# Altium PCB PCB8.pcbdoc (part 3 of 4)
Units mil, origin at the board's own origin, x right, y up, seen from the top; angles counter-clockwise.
Board outline 6799.06 x 5716.8 mil, 2 copper layers (Top Layer, Bottom Layer); 312 components, 374 nets, 1333 pads, 994 vias.
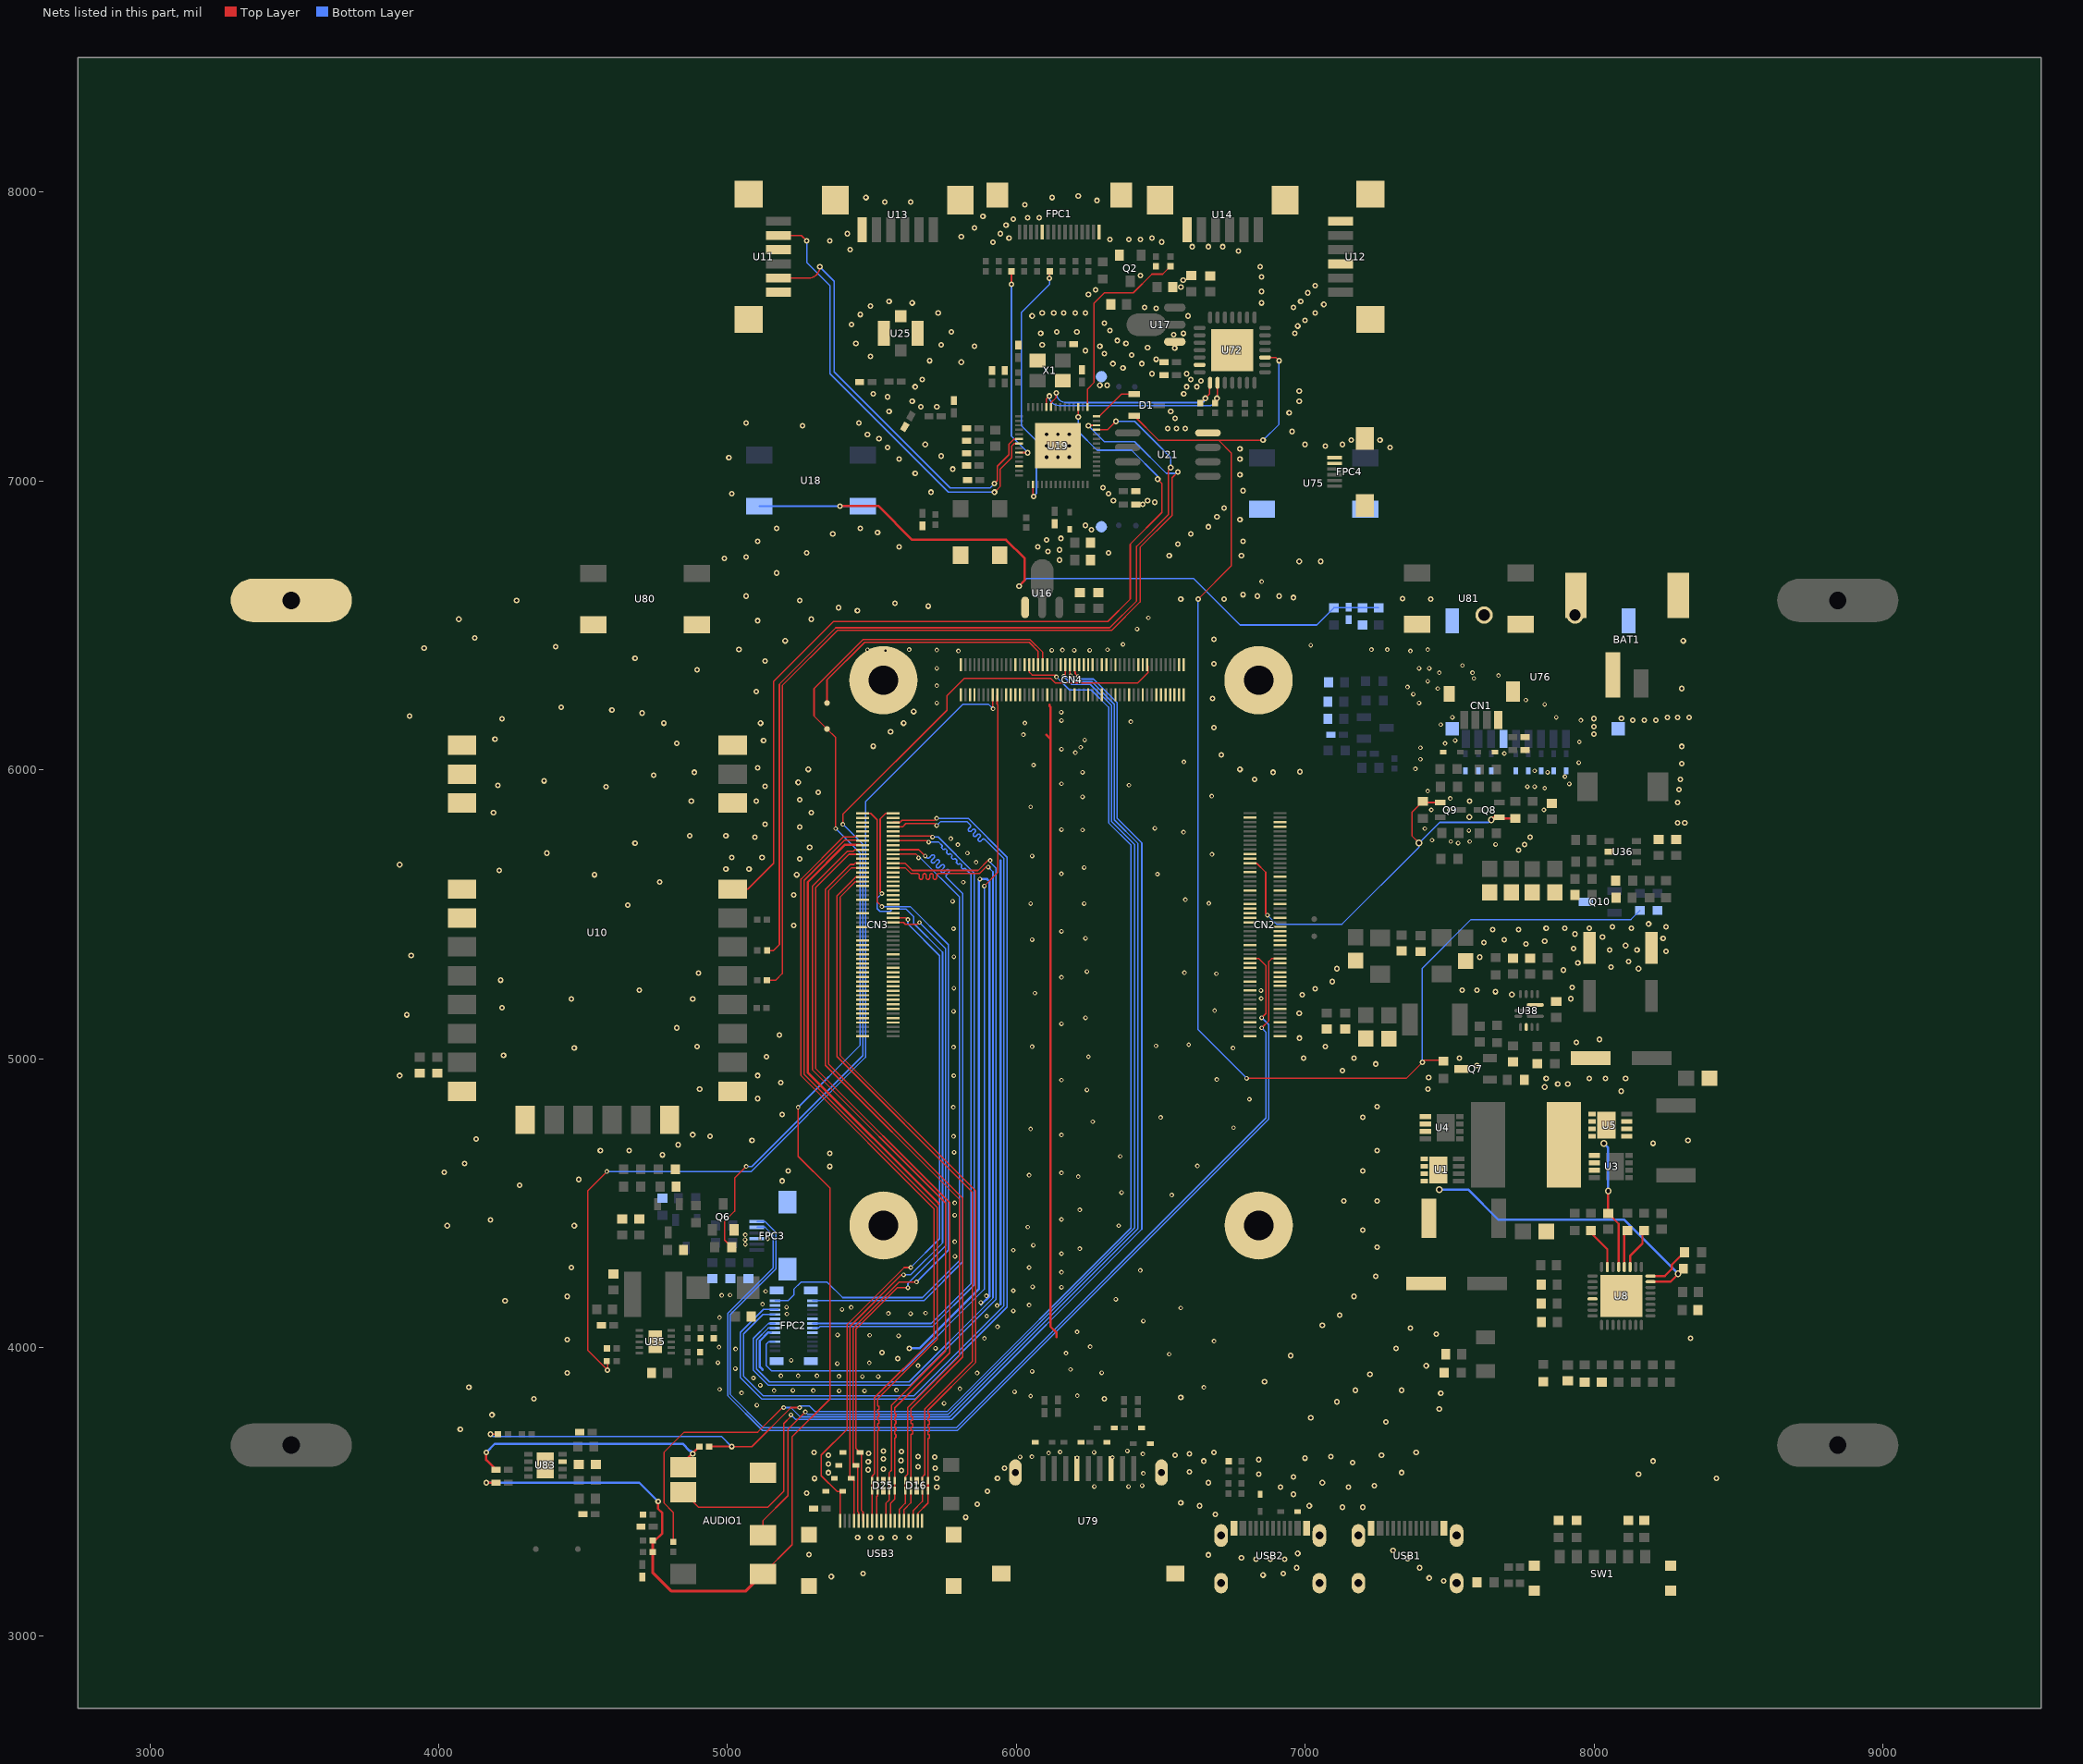
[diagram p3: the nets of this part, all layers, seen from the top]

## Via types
v1: diameter 19.7, hole 9.84, Top Layer to Bottom Layer, 526 vias
v2: diameter 15.75, hole 7.87, Top Layer to Bottom Layer, 322 vias
v3: diameter 19.68, hole 9.84, Top Layer to Bottom Layer, 98 vias
v4: diameter 23.62, hole 13.78, Top Layer to Bottom Layer, 39 vias
v5: diameter 24, hole 12, Top Layer to Bottom Layer, 9 vias

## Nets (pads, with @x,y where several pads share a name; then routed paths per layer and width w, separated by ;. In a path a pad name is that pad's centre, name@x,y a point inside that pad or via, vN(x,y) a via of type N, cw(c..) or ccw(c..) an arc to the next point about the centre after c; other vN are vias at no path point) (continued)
GND: BAT1.2 BAT1.3 BAT1.4 boot1.2 boot.2 C1.1 C2.1 C3.1 C7.1 C9.1 C10.2 C11.1 C12.2 C17.1 C18.1 C19.1 C20.1 C21.1 C22.1 C23.1 C24.1 C25.1 C26.1 C27.1 C30.2 C37.1 C38.1 C39.1 C40.1 C41.1 C42.1 C43.1 C44.1 C45.1 C46.1 C47.1 C48.1 C51.1 C52.1 C53.1 C54.1 C55.1 C56.1 C58.1 C59.1 C60.1 C61.2 C62.1 C63.1 C64.1 C71.1 C72.1 C73.1 C74.1 C75.1 C82.1 C83.1 C85.1 C86.2 C87.2 C88.1 C90.2 C91.1 C92.1 C93.1 C96.2 C97.2 C98.1 C99.1 C395.1 C397.1 C398.1 C402.2 C403.1 C404.1 C405.1 C406.2 C407.2 C408.1 C409.1 C410.1 C411.1 C412.1 C415.1 C416.1 C417.2 C418.2 C419.1 C420.1 CN1.1 CN1.5 CN1.6 CN2.1 CN2.2 CN2.7 CN2.8 CN2.13 CN2.14 CN2.22 CN2.23 CN2.32 CN2.33 CN2.42 CN2.43 CN2.52 CN2.53 CN2.59 CN2.60 CN2.65 CN2.66 CN2.71 CN2.74 CN2.98 CN3.7 CN3.8 CN3.13 CN3.14 CN3.19 CN3.20 CN3.25 CN3.26 CN3.31 CN3.32 CN3.37 CN3.38 CN3.44 CN3.50 CN3.55 CN3.56 CN3.61 CN3.62 CN3.67 CN3.68 CN3.73 CN3.74 CN3.79 CN3.80 CN3.85 CN3.86 CN3.91 CN3.92 CN3.97 CN3.98 CN4.1 CN4.2 CN4.7 CN4.13 CN4.19 CN4.22 CN4.25 CN4.31 CN4.32 CN4.37 CN4.42 CN4.43 CN4.48 CN4.49 CN4.55 CN4.56 CN4.61 CN4.62 CN4.67 CN4.68 CN4.72 CN4.73 CN4.76 CN4.99 CN4.100 D3.1 D4.1 D5.1 D6.1 D7.1 D8.1 D9.1 D10.1 D11.1 D12.1 D13.1 D14.1 D15.1 D16.3 D16.8 D17.1 D18.1 D19.1 D20.1 D21.1 D22.1 D23.1 D24.1 D25.3 D25.8 D27.2 D28.2 FPC1.1 FPC1.11 FPC1.16 FPC1.17 FPC2.5 FPC2.8 FPC2.11 FPC2.14 FPC2.17 FPC2.20 FPC2.25 FPC2.26 FPC2.27 FPC2.28 FPC3.4 FPC3.7 FPC3.8 FPC4.5 FPC4.6 FPC4.7 FPC4.8 pad.1 pad.201 pad.202 pad.203 pad.204 Q2.2 Q6.2 Q7.3 Q10.3 R6.1 R11.1 R12.2 R13.2 R14.1 R15.1 R16.2 R17.1 R22.1 R48.1 R55.1 R56.1 R66.1 R71.2 R84.1 R89.1 R91.1 R102.1 R378.1 R379.1 R382.2 R385.1 R387.1 SW1.7 SW1.8 SW1.9 SW1.10 U4.1 U4.2 U4.3 U5.1 U5.2 U5.3 U6.2 U7.2 U8.21 U8.33 U10.1 U10.2 U10.3 U10.4 U10.5 U10.11 U10.12 U10.17 U10.18 U10.26 U10.28 U11.3 U11.6 U11.7 U11.8 U12.3 U12.6 U12.7 U12.8 U13.6 U13.7 U13.8 U14.6 U14.7 U14.8 U16.1 U17.1 U19.57 U21.4 U25.2 U25.3 U25.4 U35.11 U36.2 U38.2 U38.10 U72.6 U72.29 U75.3 U75.4 U76.6 U76.G1 U76.G2 U76.G3 U76.G4 U78.2 U79.4 U79.7 U79.10 U79.11 U79.12 U79.13 U80.3 U80.4 U81.3 U81.4 U83.7 U83.9 USB1.1 USB1.2 USB1.3 USB1.4 USB1.A1 USB1.A12 USB1.B1 USB1.B12 USB2.1 USB2.2 USB2.3 USB2.4 USB2.A1 USB2.A12 USB2.B1 USB2.B12 USB3.1 USB3.4 USB3.7 USB3.10 USB3.13 USB3.20 USB3.21 X1.2 X1.4 | length 8706.8
  Top Layer w8: CN3.86@5458.2,5740.71 5407.38,5740.71 5277.48,5610.81 5277.48,4952.39 5730.88,4498.99 5730.88,4497.22 ; 6103.22,6121.68 6117.95,6106.95 ; 6114.7,6225.32 6114.7,6221.39 6117.95,6218.14 6117.95,6106.95 ; 6138.75,4036.37 6138.75,4051.79 6117.95,4072.58 6117.95,6106.95
  Bottom Layer w8: 5121.55,3922.52 5111.89,3932.18 5111.89,4022.91 5140.77,4051.79 FPC2.5@5149.59,4051.79 ; v1(5629.47,3996.49) 5664.47,3996.49 5870.35,4202.38 5870.35,5618.35 v2(5873.56,5621.56) 5898.47,5621.56 5907.37,5612.66 5907.37,4177.58 v2@5878.22,4148.44 ; 5944.84,5685.51 5945.83,5684.53 5945.83,4149.32
  other v1: 7479.47,3191.49 7429.47,3201.49 5359.47,3206.49 6854.47,3211.49 5469.47,3216.49 6924.47,3216.49 6970.64,3236.78 7396.27,3236.78 6829.47,3266.49 6929.47,3266.49 6879.27,3266.55 7354.47,3268.89 6779.47,3271.49 6664.47,3281.49 5282.31,3282.66 6974.47,3286.49 7304.47,3296.49 5532.31,3339.59 5494.47,3341.49 5579.47,3341.49 5629.47,3341.49 5450.62,3342.02 5824.47,3411.49 6689.47,3421.49 7129.47,3446.49 7199.47,3446.49 6634.47,3451.49 7014.47,3451.49 5864.47,3456.49 6569.47,3461.49 6959.47,3491.49 5274.17,3495.92 5899.47,3501.49 5724.47,3516.49 6914.47,3516.49 7149.47,3516.49 7239.47,3521.49 6664.47,3531.49 7059.47,3531.49 5300.78,3546.01 5724.47,3546.49 5934.47,3546.49 8424.47,3546.49 6959.47,3551.49 6839.47,3561.49 8154.47,3561.49 5349.47,3566.49 7334.47,3566.49 6599.5,3569.29 5601.8,3573.97 5487.37,3576.14 5539.61,3578.46 5959.47,3581.49 5719.35,3581.88 5659.47,3586.49 5349.47,3596.49 7164.47,3601.49 5487.45,3604.36 6649.47,3606.49 8204.47,3606.49 5600.76,3608.17 6839.47,3611.49 5539.61,3613.36 6999.47,3616.49 5717.73,3620.34 5659.47,3621.49 7089.47,3621.49 5349.47,3626.49 6549.47,3626.49 7264.47,3626.49 6599.47,3631.49 5488.6,3632.66 6684.47,3636.49 7384.47,3636.49 5299.05,3636.53 5601.8,3639.27 5539.61,3640.65 4074.47,3716.49 7279.47,3741.49 7019.47,3756.49 4184.47,3766.49 7464.47,3786.49 7109.47,3811.49 4329.47,3821.49 6304.47,3821.49 6569.47,3826.49 7469.47,3841.49 7174.47,3851.49 7334.47,3851.49 4104.47,3861.49 6859.47,3881.49 7224.47,3906.49 4444.47,3911.49 7419.47,3936.49 5589.47,3961.49 6949.47,3971.49 5534.47,3981.49 7314.47,3996.49 4444.47,4026.49 8334.47,4031.49 7454.47,4046.49 7364.47,4066.49 7059.47,4076.49 7119.47,4111.49 4229.47,4161.49 4444.47,4176.49 7169.47,4176.49 7244.47,4246.49 4459.47,4276.49 7249.47,4346.49 7199.47,4406.49 4029.47,4421.49 4469.47,4421.49 4179.47,4441.49 7134.47,4506.49 7249.47,4506.49 4279.47,4561.49 5189.47,4576.49 4484.47,4581.49 4019.47,4606.49 5209.47,4611.49 7199.47,4611.49 5354.47,4626.49 4089.47,4636.49 4774.47,4666.49 5354.47,4671.49 4559.47,4681.49 4659.47,4681.49 7249.47,4681.49 4829.47,4701.49 8204.47,4706.49 5084.47,4716.49 8325.59,4716.49 4129.47,4721.49 4939.47,4731.49 4879.47,4736.49 7199.47,4796.49 5189.47,4806.49 7249.47,4834.11 5104.47,4861.49 8094.47,4887.24 7425.49,4894.17 4903.3,4894.95 7829.47,4901.49 7874.47,4911.49 7909.47,4911.49 5184.47,4916.49 7834.47,4931.49 7984.47,4931.49 8039.47,4931.49 8109.47,4931.49 7427.7,4934.33 3864.47,4941.49 5104.47,4941.49 7129.07,4958.31 7594.47,4976.49 7244.47,4981.49 6994.47,5001.49 7169.47,5001.49 7534.47,5001.49 5134.47,5006.49 4224.47,5011.49 4469.47,5036.49 4894.47,5041.49 7069.47,5041.49 7939.47,5056.49 8019.47,5066.49 6980.4,5071.13 5179.47,5081.49 4824.47,5106.49 3889.47,5151.49 6979.47,5156.49 4219.47,5176.49 4459.47,5206.49 4879.47,5206.49 7919.65,5207.35 6989.47,5221.49 7715.87,5221.81 7659.47,5231.49 4694.47,5236.49 7543.82,5236.49 7594.47,5236.49 7034.47,5241.49 7924.47,5246.49 7094.47,5266.49 4214.47,5271.49 4899.47,5296.49 7894.47,5306.49 7109.47,5311.49 8154.47,5311.49 8059.47,5316.49 7944.47,5331.49 8119.47,5336.49 7604.47,5351.49 3904.47,5356.49 8249.47,5371.49 8054.47,5376.49 8149.47,5376.49 7929.47,5381.49 8109.47,5391.49 7764.47,5396.49 7619.47,5401.49 7829.47,5406.49 7689.47,5411.49 8239.47,5416.49 8029.47,5421.49 7934.47,5431.49 7649.47,5446.49 7739.47,5446.49 7834.47,5451.49 7899.47,5451.49 7984.47,5451.49 8129.47,5451.49 8064.47,5456.49 8249.47,5456.49 5229.47,5461.49 8189.47,5466.49 4654.47,5531.49 5229.47,5566.49 4764.47,5611.49 4539.47,5636.49 5239.47,5636.49 4209.47,5651.49 4994.47,5656.49 5074.47,5656.49 3864.47,5671.49 5249.47,5691.49 5014.47,5696.49 5119.47,5696.49 4374.47,5711.49 7739.47,5721.49 5284.47,5731.49 7759.47,5741.49 4679.47,5746.49 5094.47,5766.49 7779.47,5766.49 4869.47,5771.49 4994.47,5771.49 5249.47,5801.49 5129.47,5811.49 8289.47,5816.49 8314.47,5816.49 7568.45,5836.43 4189.47,5851.49 5289.47,5851.49 8289.47,5886.49 4874.47,5891.49 5099.47,5891.49 7569.47,5891.49 5249.47,5896.49 5314.47,5921.49 8294.47,5931.49 4579.47,5941.49 5129.47,5943.17 4204.47,5946.49 5244.47,5956.49 4364.47,5961.49 6824.47,5966.49 8299.47,5966.49 4744.47,5981.49 4884.47,5991.49 6889.47,5991.49 6981.71,5993.35 5279.47,6001.49 6774.47,6001.49 5104.47,6006.49 8304.47,6021.49 6709.47,6051.49 5504.47,6081.49 8304.07,6081.17 4824.47,6091.49 5124.47,6101.49 4194.47,6106.49 8000.15,6123.72 5564.47,6131.49 6684.47,6146.49 8000.15,6149.75 4779.47,6161.49 5114.47,6161.49 5609.47,6161.49 8134.47,6171.49 8174.47,6171.49 8214.47,6171.49 4219.47,6176.49 8000.15,6177.35 8095.17,6178.39 8254.47,6181.49 8289.47,6181.49 8329.47,6181.49 3899.47,6186.49 4704.47,6196.49 5644.47,6201.49 4599.47,6206.49 4424.47,6216.49 6679.47,6246.49 5099.47,6271.49 8304.47,6281.49 4894.47,6346.49 6684.47,6366.49 5129.47,6376.49 4679.47,6386.49 5039.47,6416.49 3949.47,6421.49 4404.47,6426.49 5199.47,6446.49 8309.47,6446.49 6684.47,6451.49 4124.47,6456.49 5104.47,6516.49 4069.47,6521.49 5289.47,6521.49 5449.47,6551.49 5384.47,6561.49 5694.47,6566.49 5579.47,6576.49 4269.47,6586.49 5249.47,6586.49 6569.47,6591.49 6719.47,6591.49 7434.47,6591.49 7337.32,6593.08 6959.47,6596.49 5064.47,6601.49 6834.47,6601.49 6909.47,6601.49 6784.47,6606.49 5169.47,6681.49 6979.47,6721.49 7054.47,6721.49 6149.47,6726.49 4989.47,6731.49 5064.47,6736.49 6529.47,6741.49 6779.47,6741.49 5274.47,6751.49 6319.47,6751.49 6109.47,6756.49 6149.47,6761.49 5594.47,6771.49 6074.47,6771.49 6559.47,6781.49 5104.47,6791.49 6784.47,6791.49 6104.47,6796.49 6154.47,6801.49 5364.47,6816.49 6604.47,6816.49 5519.47,6821.49 6259.47,6831.49 5169.47,6836.49 5459.47,6836.49 6664.47,6841.49 6239.47,6846.49 6774.47,6866.49 6694.47,6876.49 6719.47,6906.49 6438.2,6918.81 6479.47,6926.49 6336.09,6932.44 6454.5,6932.44 5014.47,6956.49 6319.47,6956.49 5704.47,6961.49 6784.47,6966.49 6299.47,6976.49 6774.47,7021.49 5649.47,7026.49 5779.47,7041.49 5594.47,7076.49 6774.47,7076.49 5004.47,7081.49 5739.47,7086.49 6774.47,7111.49 5554.47,7116.49 7294.47,7116.49 7069.47,7121.49 5684.47,7126.49 6999.47,7126.49 7129.47,7126.49 7159.47,7141.49 7259.47,7141.49 5524.47,7146.49 5484.47,7161.49 6954.47,7171.49 6554.47,7181.49 6584.47,7181.49 6524.47,7181.69 5259.47,7191.49 5064.47,7201.49 5454.47,7201.49 6549.47,7216.49 6944.47,7236.49 5559.47,7241.49 6534.47,7241.49 5669.47,7256.49 5724.47,7256.49 5639.47,7276.49 6979.47,7276.49 5554.47,7291.49 5504.47,7301.49 6579.47,7301.49 6979.47,7311.49 5649.47,7326.49 6589.47,7326.49 6624.47,7326.49 6289.47,7331.49 6314.47,7331.49 6639.47,7346.49 5674.47,7351.49 6604.47,7351.49 6469.47,7371.49 6589.47,7371.49 6369.47,7391.49 6334.47,7406.49 6434.47,7406.49 5809.47,7411.49 5699.47,7416.49 6483.73,7421.3 5494.47,7431.49 6399.47,7436.49 6304.47,7441.49 6239.47,7451.49 6548.67,7460.19 6454.47,7461.49 5854.47,7466.49 6289.47,7466.49 5739.47,7471.49 6089.47,7471.49 5444.47,7476.49 6379.47,7476.49 6349.47,7486.49 6544.47,7506.49 6084.47,7511.49 6578.82,7510.97 6964.47,7511.49 5774.47,7516.49 6139.47,7516.49 6209.47,7516.49 6324.47,7521.49 6974.47,7536.49 5429.47,7541.49 6304.47,7546.49 6999.47,7556.49 6054.47,7571.49 6594.47,7571.49 5459.47,7576.49 5729.47,7581.49 6089.47,7581.49 6129.47,7581.49 6164.47,7581.49 6204.47,7581.49 6239.47,7581.49 7034.47,7581.49 6483.73,7598.3 6444.47,7601.49 6959.47,7601.49 5494.47,7606.49 7064.47,7611.49 5639.47,7616.49 6849.47,7616.49 5559.47,7621.49 6984.47,7621.49 6249.47,7646.49 7009.47,7651.49 6849.47,7656.49 6274.47,7661.49 6569.8,7671.27 7034.47,7676.49 6577.69,7695.23 6849.47,7706.49 6429.47,7711.49 6844.47,7741.49 6769.47,7796.49 5424.47,7801.49 6609.47,7811.49 6664.47,7811.49 6714.47,7811.49 5919.47,7826.49 6503.15,7827.58 5354.47,7831.49 6324.47,7836.49 6389.47,7836.49 6429.47,7836.49 5974.47,7841.49 6469.47,7841.49 5809.47,7846.49 5414.47,7856.49 5944.47,7856.49 5854.47,7876.49 5964.47,7886.49 5989.47,7906.49 6039.47,7911.49 6079.47,7911.49 5884.47,7916.49 6029.88,7956.37 5544.47,7966.49 5634.47,7966.49 6279.47,7971.49 5479.47,7981.49 6124.47,7981.49 6214.47,7986.49
  other v2: 6270.18,3518.38 6388.25,3518.03 6435.94,3521.47 6439.77,3563.68 6210.39,3617.81 6332.78,3618.7 6012.9,3620.82 6053.56,3621.71 6438.01,3631.13 6111.92,3634.37 6269.47,3636.49 6151.39,3637.91 6384.47,3641.49 5101.68,3800.13 5749.47,3806.49 6049.47,3831.49 6211.27,3832.55 5048.66,3842.55 5993.9,3846.17 5386.23,3849.47 5474.31,3849.47 5296.69,3850.35 5161.18,3850.65 5226.06,3851.31 5584.78,3851.83 4972.55,3854.7 5804.47,3856.49 6649.47,3861.49 5113.76,3868.62 5089.6,3893.95 5466.8,3899.25 5521.88,3898.96 5385.5,3899.84 5184.47,3901.49 5244.47,3901.49 5309.47,3901.49 5864.47,3911.49 6295.66,3912.09 6054.47,3916.49 6187.85,3923.58 5027.23,3926.5 5659.74,3936.66 5380.07,3943.7 5490.75,3946.35 4966.58,3947.16 5220.34,3954.97 6529.47,3976.49 6171.94,3980.13 5027.67,3994.55 5720.42,3997.05 4970.56,4000.84 6255.46,4002.67 6684.47,4021.49 5889.47,4031.49 5592.06,4040.27 5492.2,4042.04 5380.73,4043.12 6210.39,4053.92 5934.47,4071.49 6439.47,4091.49 4972.11,4103.02 5897.54,4108.47 5205.5,4115.63 5633.6,4116.71 5556.72,4117.6 5685.74,4118.92 5989.47,4126.49 5396.32,4131.29 6569.47,4136.49 5204.32,4139 5428.14,4138.81 5933.47,4145 6044.47,4146.49 5121.14,4149.56 5877.01,4155.41 6344.47,4166.49 5896.1,4178.38 4979.6,4180.34 5008.76,4181.22 5131.96,4193.99 5989.47,4196.49 6156,4207.89 6056.62,4209.9 6156,4260.03 6429.47,4266.49 6044.47,4276.49 5787.12,4315.49 6156,4324.54 5989.47,4336.49 6219.47,4341.49 6058.61,4353.72 5061.91,4356.71 5786.72,4365.57 5060.93,4373.02 5138.8,4376.27 5061.33,4389.63 6039.47,4416.49 6354.47,4421.49 6156,4442.96 5786.72,4457.48 6219.47,4476.49 5786.53,4500.09 6538.33,4527.18 6364.47,4536.49 6214.47,4591.49 6044.47,4596.49 6156,4604.13 6626.81,4628.58 6359.47,4661.49 5784.55,4675.33 5782.78,4730.56 6156,4735.28 6049.47,4756.49 6752.08,4760.81 6264.47,4781.49 6499.56,4796.6 5781.45,4831.75 6806.76,4859.23 6244.47,4891.49 6156,4925.5 6694.41,4927.83 5783.22,4940.88 6249.47,5006.49 6750.09,5036.19 5782.34,5039.42 6054.47,5041.49 6483.65,5044.15 6596.99,5048.12 6156,5120.36 6239.47,5141.49 5782.78,5163.58 6686.46,5166.43 6847.7,5208.12 6064.47,5226.49 6846.99,5236.01 5783.66,5244 6156,5281.41 6692.43,5293.69 6582.07,5297.66 6244.47,5301.49 5783.66,5352.69 6054.47,5411.49 6239.47,5416.49 6156,5440.48 5782.78,5449.9 6049.47,5536.49 6234.47,5536.49 6666.58,5537.26 5779.24,5544.46 6585.06,5550.18 5816.41,5610.66 6488.62,5638.66 6155.99,5639.85 6234.47,5661.49 5860.6,5679.68 6054.47,5701.49 6677.51,5707.26 5830.75,5711.5 5797.36,5740.56 7659.47,5741.49 7529.47,5746.49 7504.47,5751.49 7569.47,5751.49 7439.47,5756.49 5772.81,5761.77 6579.09,5783.81 7566.86,5789.43 6229.47,5791.49 6156,5792.86 7414.47,5796.49 6479.67,5797.73 7437.1,5861.2 7499.47,5861.49 7826.51,5861.2 6049.47,5871.49 7502.76,5900.57 6229.47,5906.49 6676.52,5909.08 7424.47,5926.49 7829.47,5936.49 7769.47,5941.49 7794.47,5941.49 6390.2,5946.86 7914.47,5951.49 6156,5951.72 7899.47,5976.49 6229.47,5991.49 7839.47,5991.49 7794.47,5996.49 7381.98,6003.39 6059.47,6016.49 7947.56,6024.58 6580.08,6027.39 7399.47,6036.49 7689.47,6056.49 6204.38,6059.28 6156,6071.17 7399.47,6076.49 6222.65,6078.13 7484.47,6091.49 7949.47,6096.49 7519.47,6101.49 6236.79,6103.17 6024.47,6121.49 7469.47,6156.49 6029.47,6161.49 6396.16,6166.57 6156,6170.46 7954.47,6171.49 7509.47,6181.49 7869.47,6181.49 6155.84,6199.4 7829.47,6226.49 5724.47,6231.49 7394.47,6231.49 7764.47,6241.49 7374.47,6261.49 7459.47,6281.49 7354.47,6286.49 5724.47,6291.49 7424.47,6306.49 7584.47,6316.49 7669.47,6326.49 7464.47,6336.49 7579.47,6336.49 5724.47,6351.49 7394.47,6351.49 7429.47,6351.49 7544.47,6361.49 5799.47,6411.49 7364.47,6411.49 5547.37,6412.66 6122.67,6413.98 6159.78,6414.42 6200.43,6413.98 6253.9,6413.98 5484.63,6415.31 5724.56,6414.87 5629.11,6416.19 6315.76,6415.75 7229.47,6416.49 7284.47,6416.49 7424.47,6416.49 7019.47,6431.49 6369.22,6434.31 6417.83,6487.33 6457.15,6526.21 6849.47,6651.49
  other v5: 6104.45,7082.77 6143.84,7082.79 6183.19,7082.77 6104.46,7122.15 6143.82,7122.14 6183.19,7122.14 6104.46,7161.51 6143.82,7161.51 6183.19,7161.51
GPIO_VREF: CN2.78 Q8.1 Q9.1 R94.2 R103.2 | length 1472.3
  Top Layer w5: CN2.78@6821.49,5676.47 6832.09,5676.47 6863.51,5645.06 6863.51,5502.45 v2(6869.47,5496.49) ; v4(7394.47,5746.49) 7369.47,5771.49 7369.47,5852.57 R103.2@7407.76,5890.86
  Top Layer w7.87: R103.2@7407.76,5890.86 7411.83,5886.79 Q9.1@7467.41,5886.79 ; Q8.1@7673.11,5835.61 7677.18,5831.54 R94.2@7727.76,5831.54
  Top Layer w10: v4(7644.47,5826.49) 7653.58,5835.61 Q8.1@7673.11,5835.61
  Bottom Layer w5: v2(6869.47,5496.49) 6900.38,5465.59 7127.62,5465.59 7394.47,5732.43 v4(7394.47,5746.49) 7466.06,5818.08 7636.06,5818.08 v4(7644.47,5826.49)
HDMI_TX0N_PORT: CN3.84 D25.2 D25.9 USB3.9 | length 2708.7
  Top Layer w5: CN3.84@5475.01,5723.57 5441.25,5723.57 5436.25,5718.57 5416.01,5718.57 5293.48,5596.04 5293.48,4961.92 5755.33,4500.08 5755.33,3987.35 5567.85,3799.88 5567.85,3574.88 5559.15,3566.17 D25.2@5559.15,3538.53 5559.47,3538.21 5559.47,3471.49 5548.06,3460.08 USB3.9@5548.06,3399.09
HDMI_TX0P_PORT: CN3.82 D25.1 D25.10 USB3.8 | length 2706.7
  Top Layer w5: CN3.82@5473.62,5706.43 5472.48,5707.57 5420.55,5707.57 5304.47,5591.49 5304.47,4966.49 5769.47,4501.49 5769.47,3981.49 5578.84,3790.86 5578.84,3773 ccw(c5580.84,3773) 5580.84,3771 cw(c5580.84,3769) 5582.84,3769 5582.84,3761 cw(c5580.84,3761) 5580.84,3759 ccw(c5580.84,3757) 5578.84,3757 5578.84,3749 ccw(c5580.84,3749) 5580.84,3747 cw(c5580.84,3745) 5582.84,3745 5582.84,3737 cw(c5580.84,3737) 5580.84,3735 ccw(c5580.84,3733) 5578.84,3733 5578.84,3725 ccw(c5580.84,3725) 5580.84,3723 cw(c5580.84,3721) 5582.84,3721 5582.84,3713 cw(c5580.84,3713) 5580.84,3711 ccw(c5580.84,3709) 5578.84,3709 5578.84,3701 ccw(c5580.84,3701) 5580.84,3699 cw(c5580.84,3697) 5582.84,3697 5582.84,3689 cw(c5580.84,3689) 5580.84,3687 ccw(c5580.84,3685) 5578.84,3685 D25.1@5578.84,3538.53 5579.47,3537.9 5579.47,3475.01 5563.8,3459.34 USB3.8@5563.8,3399.09
HDMI_TX1N_PORT: CN3.78 D16.5 D16.6 USB3.6 | length 2641.2
  Top Layer w5: CN3.78@5476.07,5677.39 5442.48,5677.39 5437.48,5672.39 5424.84,5672.39 5338.48,5586.04 5338.48,4976.94 5803.48,4511.94 5803.48,3971.04 5623.79,3791.35 5623.79,3560.82 5615.1,3552.12 D16.5@5615.1,3538.53 D16.6@5615.1,3504.45 5615.1,3459.98 5595.3,3440.18 USB3.6@5595.3,3399.09
HDMI_TX1P_PORT: CN3.76 D16.4 D16.7 USB3.5 | length 2642.3
  Top Layer w5: CN3.76@5476.01,5661.58 5475.4,5660.97 5428.95,5660.97 5349.47,5581.49 5349.47,4981.49 5814.47,4516.49 5814.47,3966.49 5634.78,3786.8 5634.78,3763.28 ccw(c5638.18,3763.28) 5638.18,3759.88 cw(c5638.18,3756.48) 5641.58,3756.48 5641.58,3751.28 cw(c5638.18,3751.28) 5638.18,3747.88 ccw(c5638.18,3744.48) 5634.78,3744.48 5634.78,3739.28 ccw(c5638.18,3739.28) 5638.18,3735.88 cw(c5638.18,3732.48) 5641.58,3732.48 5641.58,3727.28 cw(c5638.18,3727.28) 5638.18,3723.88 ccw(c5638.18,3720.48) 5634.78,3720.48 5634.78,3715.28 ccw(c5638.18,3715.28) 5638.18,3711.88 cw(c5638.18,3708.48) 5641.58,3708.48 5641.58,3703.28 cw(c5638.18,3703.28) 5638.18,3699.88 ccw(c5638.18,3696.48) 5634.78,3696.48 D16.4@5634.78,3538.53 5634.47,3538.22 5634.47,3461.49 5611.05,3438.07 USB3.5@5611.05,3399.09
HDMI_TX2N_PORT: CN3.72 D16.2 D16.9 USB3.3 | length 2570.1
  Top Layer w5: CN3.72@5476.02,5630.76 5474.64,5629.37 5444.22,5629.37 5378.48,5563.64 5378.48,5006.94 5848.48,4536.94 5848.48,3952.64 5682.85,3787.01 5682.85,3559.88 5674.15,3551.17 D16.2@5674.15,3538.53 5674.47,3538.21 5674.47,3466.49 5642.54,3434.56 USB3.3@5642.54,3399.09
HDMI_TX2P_PORT: CN3.70 D16.1 D16.10 USB3.2 | length 2571.7
  Top Layer w5: CN3.70@5474.9,5613.57 5474.11,5612.78 5443.18,5612.78 5389.47,5559.07 5389.47,5011.49 5859.47,4541.49 5859.47,3948.09 5693.84,3782.46 5693.84,3772.12 ccw(c5696.65,3772.12) 5696.65,3769.3 cw(c5696.65,3766.49) 5699.47,3766.49 5699.47,3760.12 cw(c5696.65,3760.12) 5696.65,3757.3 ccw(c5696.65,3754.49) 5693.84,3754.49 5693.84,3748.12 ccw(c5696.65,3748.12) 5696.65,3745.3 cw(c5696.65,3742.49) 5699.47,3742.49 5699.47,3736.12 cw(c5696.65,3736.12) 5696.65,3733.3 ccw(c5696.65,3730.49) 5693.84,3730.49 5693.84,3724.12 ccw(c5696.65,3724.12) 5696.65,3721.3 cw(c5696.65,3718.49) 5699.47,3718.49 5699.47,3712.12 cw(c5696.65,3712.12) 5696.65,3709.3 ccw(c5696.65,3706.49) 5693.84,3706.49 5693.84,3700.12 ccw(c5696.65,3700.12) 5696.65,3697.3 cw(c5696.65,3694.49) 5699.47,3694.49 5699.47,3688.12 cw(c5696.65,3688.12) 5696.65,3685.3 ccw(c5696.65,3682.49) 5693.84,3682.49 D16.1@5693.84,3538.53 ; USB3.2@5658.29,3399.09 5658.29,3425.31 5693.84,3460.86 D16.10@5693.84,3504.45
  Top Layer w7.9: D16.10@5693.84,3504.45 D16.1@5693.84,3538.53
HDMI_TX_CEC_PORT: CN3.51 D12.2 USB3.14 | length 2369.7
  Top Layer w5: USB3.14@5469.32,3399.09 5469.32,3429.8 5464.32,3434.8 5464.32,3631.17 5444.47,3651.02 5444.47,4063.76 5587.2,4206.49 v2(5624.47,4206.49) ; CN3.51@5571.09,5471.6 5609.58,5471.6 5616.06,5465.12 5658.09,5465.12 v2(5664.47,5471.49)
  Bottom Layer w5: v2(5624.47,4206.49) 5624.47,4221.49 5755.47,4352.49 5755.47,5380.49 v2(5664.47,5471.49)
HDMI_TX_HPD_PORT: CN3.53 D15.2 USB3.19 | length 2416.8
  Top Layer w5: USB3.19@5390.58,3399.09 5390.58,3497.6 D15.2@5394.47,3501.49 ; D15.2@5403.99,3501.49 D15.2@5394.47,3501.49 ; CN3.53@5571.19,5487.25 5571.45,5487.51 5618.45,5487.51 v2(5624.47,5481.49) ; v2(5634.47,4276.49) 5611.31,4276.49 5414.47,4079.65 5414.47,3717.44 5324.47,3627.44 5324.47,3555.45 5378.43,3501.49 D15.2@5394.47,3501.49
  Bottom Layer w5: v2(5624.47,5481.49) 5624.47,5466.49 5734.47,5356.49 5734.47,4376.49 v2(5634.47,4276.49)
HDMI_TXCLKN_PORT: CN3.90 D25.5 D25.6 USB3.12 | length 2783.6
  Top Layer w5: CN3.90@5474.11,5771.05 5442.74,5771.05 5438.64,5766.95 5399.92,5766.95 5254.47,5621.49 5254.47,4940.96 5714.47,4480.96 5714.47,4032.03 5508.48,3826.04 5508.48,3562.51 5500.1,3554.12 D25.5@5500.1,3538.53 5500.81,3537.82 USB3.12@5500.81,3399.09
HDMI_TXCLKP_PORT: CN3.88 D25.4 D25.7 USB3.11 | length 2784.3
  Top Layer w5: CN3.88@5475.89,5755.95 5404.46,5755.95 5265.45,5616.94 5265.45,4945.51 5725.45,4485.51 5725.45,4027.48 5519.78,3821.8 5519.78,3798.63 ccw(c5522.12,3798.63) 5522.12,3796.28 cw(c5522.12,3793.94) 5524.47,3793.94 5524.47,3786.63 cw(c5522.12,3786.63) 5522.12,3784.28 ccw(c5522.12,3781.94) 5519.78,3781.94 5519.78,3774.63 ccw(c5522.12,3774.63) 5522.12,3772.28 cw(c5522.12,3769.94) 5524.47,3769.94 5524.47,3762.63 cw(c5522.12,3762.63) 5522.12,3760.28 ccw(c5522.12,3757.94) 5519.78,3757.94 5519.78,3750.63 ccw(c5522.12,3750.63) 5522.12,3748.28 cw(c5522.12,3745.94) 5524.47,3745.94 5524.47,3738.63 cw(c5522.12,3738.63) 5522.12,3736.28 ccw(c5522.12,3733.94) 5519.78,3733.94 5519.78,3726.63 ccw(c5522.12,3726.63) 5522.12,3724.28 cw(c5522.12,3721.94) 5524.47,3721.94 5524.47,3714.63 cw(c5522.12,3714.63) 5522.12,3712.28 ccw(c5522.12,3709.94) 5519.78,3709.94 D25.4@5519.78,3538.53 5519.47,3538.22 5519.47,3486.49 5516.56,3483.58 USB3.11@5516.56,3399.09
HDMI_TXDDC_SCL_PORT: CN3.100 D13.2 USB3.15 | length 2829.1
  Top Layer w5: D13.2@5443.99,3591.49 5434.47,3601.02 5434.47,4066.49 5594.47,4226.49 v2(5654.47,4226.49) ; D13.2@5450.26,3596.71 5450.26,3431.89 5453.57,3428.57 USB3.15@5453.57,3399.09 ; CN3.100@5468.21,5849.56 5495.65,5849.56 5518.09,5827.12 5518.09,5542.87 v2(5534.47,5526.49)
  Bottom Layer w5: v2(5534.47,5526.49) 5632.62,5526.49 5764.47,5394.65 5764.47,4336.49 v2(5654.47,4226.49)
HDMI_TXDDC_SDA_PORT: CN3.99 D14.2 USB3.16 | length 2807.6
  Top Layer w5: USB3.16@5437.82,3399.09 5437.82,3537.67 D14.2@5428.99,3546.49 5423.68,3551.8 5423.68,4072.78 5602.4,4251.49 v2(5609.47,4251.49) ; v2(5534.47,5571.49) 5528.47,5577.49 5528.47,5830.04 5547.99,5849.56 CN3.99@5572.93,5849.56
  Bottom Layer w5: v2(5534.47,5571.49) 5518.09,5555.12 5518.09,5519.71 5527.69,5510.12 5563.09,5510.12 5570.45,5517.48 5618.48,5517.48 5644.47,5491.49 5644.47,5468.34 5744.47,5368.34 5744.47,4361.49 5634.47,4251.49 v2(5609.47,4251.49)
HG1: R2.2 U8.8 | length 159.8
  Top Layer w7.87: U8.8@8195.9,4246.99 8244.97,4246.99 8269.47,4271.49 8269.47,4285.99 R2.2@8313.02,4329.53
HG2: R7.1 U8.15 | length 150.2
  Top Layer w7.87: R7.1@7989.68,4405.21 7989.68,4396.28 8046.3,4339.67 U8.15@8046.3,4278.49
HP_DET_L_GPIO4_C4: CN4.70 R52.2 R384.2 | length 4871
  Top Layer w5: v3(4179.47,3699.41) R384.2@4205.24,3699.41 ; v3(5014.47,3656.49) 5084.47,3656.49 5219.47,3791.49 v2(5249.47,3791.49) ; CN4.70@6041.79,6380.23 6044.11,6377.91 6044.11,6338.92 6054.76,6328.27 6132.36,6328.27 v2(6138.65,6321.98)
  Top Layer w6: R52.2@4936.51,3656.49 v3(5014.47,3656.49)
  Bottom Layer w5: v2(5249.47,3791.49) 5254.47,3796.49 5284.47,3796.49 5303.47,3777.49 5760.41,3777.49 6396.46,4413.53 6396.46,5739.5 6319.47,5816.49 6319.47,6216.49 6259.47,6276.49 6184.14,6276.49 v2(6138.65,6321.98)
  Bottom Layer w6: v3(4179.47,3699.41) 4187.39,3691.49 4979.47,3691.49 v3(5014.47,3656.49)
HP_SNS: CN4.52 R50.2 | length 4395.8
  Top Layer w5: R50.2@4812.43,3326.49 4812.43,3428.53 4779.47,3461.49 4779.47,3636.49 4849.47,3706.49 5104.66,3706.49 5189.66,3791.49 v2(5194.47,3791.49) ; CN4.52@6185.73,6363.54 6185.73,6325.93 v2(6188.71,6325.93)
  Bottom Layer w5: v2(5194.47,3791.49) 5219.47,3791.49 5251.47,3759.49 5769.28,3759.49 6421.46,4411.66 6421.46,5744.5 6339.47,5826.49 6339.47,6226.85 6261.2,6305.12 6207.69,6305.12 6188.71,6324.09 v2(6188.71,6325.93)
HPL: AUDIO1.5 C413.1 R52.1 | length 911.5
  Top Layer w7.87: v3(4164.47,3636.49) 4164.47,3610.03 C413.1@4198.01,3576.49 ; AUDIO1.5@4846.67,3585.49 4846.67,3600.73 R52.1@4902.43,3656.49
  Bottom Layer w7.87: v3(4164.47,3636.49) 4194.47,3666.49 4844.47,3666.49 4869.47,3641.49 cw(c4869.47,3631.49) v3(4879.47,3631.49)
HPL_OUT: AUDIO1.4 CN4.50 | length 4239.1
  Top Layer w5: AUDIO1.4@4846.67,3498.87 4899.05,3446.49 5139.47,3446.49 5194.47,3501.49 5194.47,3736.49 5219.47,3761.49 v2(5219.47,3766.49) ; CN4.50@6201.48,6363.54 6201.48,6342.1 6203.95,6339.62 6203.95,6332.55 v2(6213.6,6322.9)
  Bottom Layer w5: v2(5219.47,3766.49) 5235.47,3750.49 5775.96,3750.49 6434.47,4409 6434.47,5746.49 6349.47,5831.49 6349.47,6231.49 6266.84,6314.12 6222.38,6314.12 v2(6213.6,6322.9)
HPR: AUDIO1.6
HPR_OUT: AUDIO1.3 CN4.54 | length 3982.8
  Top Layer w5: AUDIO1.3@5122.27,3349.27 5122.27,3399.29 5209.47,3486.49 5209.47,3716.49 v2(5269.47,3776.49) ; v2(6164.58,6323.22) 6169.58,6328.22 CN4.54@6169.58,6356.6
  Bottom Layer w5: v2(5269.47,3776.49) 5277.47,3768.49 5764.14,3768.49 6409.47,4413.82 6409.47,5741.49 6329.47,5821.49 6329.47,6222.71 6256.06,6296.12 6191.68,6296.12 v2(6164.58,6323.22)
I2C0_SCL_PMIC: CN2.80
I2C0_SDA_PMIC: CN2.82
I2C2_SCL_M1: CN2.35 FPC3.1 | length 3656.8
  Top Layer w5: v2(6849.47,5106.49) 6874.47,5131.49 6874.47,5336.49 6884,5346.02 CN2.35@6913.48,5346.02
  Bottom Layer w5: FPC3.1@5101.74,4435.63 5129.83,4435.63 5167.2,4398.25 5167.2,4271.47 5009.47,4113.74 5009.47,3836.49 5124.47,3721.49 5791.72,3721.49 6864.47,4794.24 6864.47,5091.49 v2(6849.47,5106.49)
I2C2_SCL_MO: CN2.56
I2C2_SDA_M1: CN2.36 FPC3.2 | length 3671.1
  Top Layer w5: CN2.36@6808.76,5346.02 6809.23,5346.49 6839.47,5346.49 6864.47,5321.49 6864.47,5156.49 v2(6849.47,5141.49)
  Bottom Layer w5: FPC3.2@5101.74,4415.94 5129.83,4415.94 5158.2,4387.56 5158.2,4275.22 5000.45,4117.48 5000.45,3832.78 5120.74,3712.49 5795.47,3712.49 6873.48,4790.51 6873.48,5117.48 v2(6849.47,5141.49)
I2C2_SDA_MO: CN2.58
I2C3_SCL_TP: CN4.44
I2C3_SDA_TP: CN4.46
I2S1_LRCK_RX_M1: CN2.29
I2S1_LRCK_TX_M1: CN2.26
I2S1_MCLK_M1: CN2.41
I2S1_SCLK_TX_M1: CN2.49
I2S1_SDI0_M1: CN2.27
I2S1_SDI1_M1: CN2.45
I2S1_SDI2_M1: CN2.47
I2S1_SDI3_M1: CN2.54
I2S1_SDO0_M1: CN2.25
I2S1_SDO2_M1: CN2.34
INT: R33.2 U19.9 | length 681.1
  Top Layer w5: v3(5982.98,7681.49) R33.2@5982.98,7726.46 ; U19.9@6009.66,7098.53 6038.04,7098.53 v3(6038.75,7097.82)
  Bottom Layer w5: v3(5982.98,7681.49) 5982.98,7155.3 6038.75,7099.53 v3(6038.75,7097.82)
LCD0_BL_EN: CN4.75
LCD0_BL_PWM5: CN4.95
LCD1_PWREN_H: CN4.4
LEDA1: R47.2 U19.43 | length 686.5
  Top Layer w5: U19.43@6246.18,7256.3 6246.18,7318.2 6269.47,7341.49 6269.47,7616.49 6304.47,7651.49 6404.47,7651.49 6469.47,7716.49 6506.49,7716.49 R47.2@6533.52,7743.52
LG1: R9.1 U8.11 | length 144.5
  Top Layer w7.87: U8.11@8125,4278.49 8125,4317.02 8168.02,4360.04 R9.1@8168.02,4405.21
LG2: R10.1 U8.12 | length 129.2
  Top Layer w7.87: U8.12@8105.3,4278.49 8105.3,4399.16 R10.1@8111.35,4405.21
LX: U11.2 U19.7 | length 1553.2
  Top Layer w5: U11.2@5175.65,7850.32 5255.64,7850.32 v3(5274.47,7831.49) ; v3(5924.47,6961.49) 5944.47,6981.49 5944.47,7041.49 5984.47,7081.49 5984.47,7121.49 5993,7130.02 U19.7@6009.66,7130.02
  Bottom Layer w5: v3(5274.47,7831.49) 5274.47,7756.49 5354.47,7676.49 5354.47,7371.49 5764.47,6961.49 v3(5924.47,6961.49)
LX2: C5.2 L1.2 U3.1 U3.2 U3.3 U5.5 U5.6 U5.7 U5.8 U8.13 | length 449.2
  Top Layer w7.87: v4(8049.47,4541.49) C5.2@8049.47,4464.05 8085.7,4427.83 U8.13@8085.7,4278.49
  Bottom Layer w7.87: v4(8034.47,4706.49) 8049.47,4691.49 v4(8049.47,4541.49)
LY: U11.5 U19.6 | length 1477
  Top Layer w5: U11.5@5175.65,7702.68 5280.65,7702.68 ccw(c5280.65,7741.49) v3(5319.47,7741.49) ; v3(5923.62,6990.94) 5934.47,7001.79 5934.47,7051.49 5974.47,7091.49 5974.47,7127.61 5992.63,7145.77 U19.6@6009.66,7145.77
  Bottom Layer w5: v3(5319.47,7741.49) 5369.47,7691.49 5369.47,7378.14 5771.12,6976.49 5909.17,6976.49 v3(5923.62,6990.94)
MIC1_IN: AUDIO1.1 C414.1 CN4.64 R54.1 R57.1 TP1.1 | length 5643.1
  Top Layer w5: AUDIO1.1@5122.27,3215.41 5223.47,3316.61 5223.47,3690.49 5354.47,3821.49 5354.47,4551.49 5244.47,4661.49 v2(5244.47,4831.49) ; v2(5374.47,5796.49) 5374.47,6111.49 TP1.1@5344.47,6141.49 5299.47,6186.49 5299.47,6281.49 5468.48,6450.51 6048.18,6450.51 6091.6,6407.09 CN4.64@6091.6,6365.59
  Top Layer w7.87: v3(4164.47,3531.49) C414.1@4198.01,3531.49 ; R54.1@4741.51,3331.49 4749.47,3331.49 4774.47,3356.49 4774.47,3426.49 4759.47,3441.49 v3(4759.47,3466.49)
  Top Layer w10: R54.1@4741.51,3331.49 R57.1@4741.51,3291.49 4741.51,3219.45 4804.47,3156.49 5063.35,3156.49 AUDIO1.1@5122.27,3215.41
  Bottom Layer w5: v2(5244.47,4831.49) 5459.47,5046.49 5459.47,5711.49 v2(5374.47,5796.49)
  Bottom Layer w7.87: v3(4164.47,3531.49) 4694.47,3531.49 v3(4759.47,3466.49)
MIC2_IN: CN4.66 TP2.1 | length 926.3
  Top Layer w5: TP2.1@5344.47,6231.49 5344.47,6311.49 5474.47,6441.49 6044.47,6441.49 6075.38,6410.58 CN4.66@6075.38,6361.8
MIPI_BL_EN_1: CN4.85 R381.2 | length 3349.2
  Top Layer w5: R381.2@4581.6,3952.01 4584.47,3949.14 v1(4584.47,3921.49) 4515.7,3990.26 4515.7,4542.47 v2(4582.06,4608.83) ; CN4.85@5918.36,6253.15 5918.36,6212.6 v2(5919.47,6211.49)
  Bottom Layer w5: v2(4582.06,4608.83) 5081.81,4608.83 5477.47,5004.49 5477.47,5889.49 5814.47,6226.49 5904.47,6226.49 v2(5919.47,6211.49)
MIPI_BL_EN_2: CN4.77
MIPI_CSI_RX_CLK0N: CN3.27
MIPI_CSI_RX_CLK0P: CN3.29
MIPI_CSI_RX_CLK1N: CN3.40
MIPI_CSI_RX_CLK1P: CN3.42
MIPI_CSI_RX_D0N: CN3.15
MIPI_CSI_RX_D0P: CN3.17
MIPI_CSI_RX_D1N: CN3.21
MIPI_CSI_RX_D1P: CN3.23
MIPI_CSI_RX_D2N: CN3.28
MIPI_CSI_RX_D2P: CN3.30
MIPI_CSI_RX_D3N: CN3.34
MIPI_CSI_RX_D3P: CN3.36
MIPI_DSI_TX0_CLKN/LVDS_TX0_CLKN: CN3.69
MIPI_DSI_TX0_CLKP/LVDS_TX0_CLKP: CN3.71
MIPI_DSI_TX0_D0N/LVDS_TX0_D0N: CN3.57
MIPI_DSI_TX0_D0P/LVDS_TX0_D0P: CN3.59
MIPI_DSI_TX0_D1N/LVDS_TX0_D1N: CN3.63
MIPI_DSI_TX0_D1P/LVDS_TX0_D1P: CN3.65
MIPI_DSI_TX0_D2N/LVDS_TX0_D2N: CN4.3
MIPI_DSI_TX0_D2P/LVDS_TX0_D2P: CN4.5
MIPI_DSI_TX0_D3N/LVDS_TX0_D3N: CN4.9
MIPI_DSI_TX0_D3P/LVDS_TX0_D3P: CN4.11
MIPI_DSI_TX1_CLKN: CN3.87 FPC2.18 | length 2383.3
  Top Layer w5: CN3.87@5572.93,5755.07 5690.91,5755.07 v2(5696.52,5749.47)
  Bottom Layer w5: FPC2.18@5293.6,4082.75 5705.17,4082.75 5843.21,4220.79 5843.21,5637.75 5823.79,5657.17 ccw(c5821.27,5654.66) 5818.75,5657.17 cw(c5816.24,5659.69) 5813.72,5657.17 5810.27,5660.62 cw(c5812.79,5663.14) 5810.27,5665.66 ccw(c5807.75,5668.17) 5810.27,5670.69 5806.82,5674.14 ccw(c5804.3,5671.63) 5801.78,5674.14 cw(c5799.27,5676.66) 5796.75,5674.14 5793.3,5677.59 cw(c5795.82,5680.11) 5793.3,5682.63 ccw(c5790.78,5685.15) 5793.3,5687.66 5789.85,5691.11 ccw(c5787.33,5688.6) 5784.81,5691.11 cw(c5782.3,5693.63) 5779.78,5691.11 5776.33,5694.56 cw(c5778.85,5697.08) 5776.33,5699.6 ccw(c5773.81,5702.12) 5776.33,5704.63 5772.88,5708.08 ccw(c5770.36,5705.57) 5767.84,5708.08 cw(c5765.33,5710.6) 5762.81,5708.08 5759.36,5711.53 cw(c5761.87,5714.05) 5759.36,5716.57 ccw(c5756.84,5719.09) 5759.36,5721.6 5755.91,5725.05 ccw(c5753.39,5722.54) 5750.87,5725.05 cw(c5748.36,5727.57) 5745.84,5725.05 5742.39,5728.51 cw(c5744.9,5731.02) 5742.39,5733.54 ccw(c5739.87,5736.06) 5742.39,5738.57 5731.49,5749.47 v2(5696.52,5749.47)
MIPI_DSI_TX1_CLKP: CN3.89 FPC2.19 | length 2383
  Top Layer w5: CN3.89@5572.93,5770.82 5706.09,5770.82 v2(5709.48,5767.43)
  Bottom Layer w5: FPC2.19@5293.6,4067 5314.98,4067 5319.73,4071.75 5709.73,4071.75 5854.19,4216.22 5854.19,5642.3 5729.06,5767.43 v2(5709.48,5767.43)
MIPI_DSI_TX1_D0N: CN3.75 FPC2.6 | length 3077.2
  Top Layer w5: CN3.75@5570.66,5661.01 5614.95,5661.01 5635.45,5640.51 5657.96,5640.51 cw(c5657.96,5634.51) 5663.96,5634.51 5663.96,5626.48 ccw(c5669.96,5626.48) 5675.96,5626.48 5675.96,5634.51 cw(c5681.96,5634.51) 5687.96,5634.51 5687.96,5626.48 ccw(c5693.96,5626.48) 5699.96,5626.48 5699.96,5634.51 cw(c5705.96,5634.51) 5711.96,5634.51 5711.96,5626.48 ccw(c5717.96,5626.48) 5723.96,5626.48 5723.96,5634.51 cw(c5729.96,5634.51) 5729.96,5640.51 5871.97,5640.51 5894.72,5663.26 v2(5902.5,5663.26)
  Bottom Layer w5: FPC2.6@5164.47,4067 5141.11,4067 5100.47,4026.36 5100.47,3925.49 5145.23,3880.73 5628.71,3880.73 5919.07,4171.1 5919.07,5646.69 v2(5902.5,5663.26)
MIPI_DSI_TX1_D0P: CN3.77 FPC2.7 | length 3083.2
  Top Layer w5: CN3.77@5570.83,5676.59 5614.93,5676.59 5640.01,5651.51 5867.41,5651.51 5902.4,5686.49 v2(5909.47,5686.49)
  Bottom Layer w5: FPC2.7@5164.47,4082.75 5141.31,4082.75 5089.47,4030.92 5089.47,3920.96 5140.69,3869.73 5633.24,3869.73 5930.07,4166.56 5930.07,5658.85 5909.47,5679.45 v2(5909.47,5686.49)
MIPI_DSI_TX1_D1N: CN3.81 FPC2.12 | length 2308.4
  Top Layer w5: CN3.81@5570.98,5707.93 5653.06,5707.93 5661.36,5699.62 v2(5661.36,5694.86)
  Bottom Layer w5: FPC2.12@5164.47,4161.49 5209.47,4161.49 5229.47,4181.49 5229.47,4201.49 5254.47,4226.49 5344.47,4226.49 5398.47,4172.49 5674.91,4172.49 5803.47,4301.05 5803.47,5559.34 5667.94,5694.86 v2(5661.36,5694.86)
MIPI_DSI_TX1_D1P: CN3.83 FPC2.13 | length 2304
  Top Layer w5: CN3.83@5572.93,5723.58 5662.38,5723.58 v2(5684.47,5701.49)
  Bottom Layer w5: FPC2.13@5293.6,4161.49 5679.47,4161.49 5814.47,4296.49 5814.47,5571.49 5758.07,5627.89 cw(c5762.31,5632.13) 5758.07,5636.37 5766.28,5644.58 ccw(c5762.04,5648.83) 5757.8,5653.07 5749.59,5644.86 cw(c5745.34,5649.1) 5741.1,5653.34 5749.31,5661.56 ccw(c5745.07,5665.8) 5740.83,5670.04 5732.62,5661.83 cw(c5728.37,5666.07) 5724.13,5670.32 5732.34,5678.53 ccw(c5728.1,5682.77) 5723.86,5687.01 5715.65,5678.8 cw(c5711.4,5683.04) 5707.16,5687.29 5715.37,5695.5 ccw(c5711.13,5699.74) 5706.89,5703.98 5698.68,5695.77 ; v2(5684.47,5701.49) 5690.19,5695.77 ccw(c5694.43,5700.01) 5698.67,5695.77
MIPI_DSI_TX1_D2N: CN3.93 FPC2.9 | length 3422.9
  Top Layer w5: CN3.93@5572.93,5802.32 5605.93,5802.32 5617.48,5813.88 5717.68,5813.88 v2(5724.17,5807.38)
  Bottom Layer w5: FPC2.9@5164.47,4114.25 5122.78,4114.25 5055.47,4046.94 5055.47,3900.49 5123.47,3832.49 5645.47,3832.49 5957.09,4144.12 5957.09,5692.6 5890.98,5758.72 ccw(c5886.73,5754.48) 5882.49,5758.72 5877.71,5753.93 cw(c5873.46,5758.18) 5869.22,5762.42 5874.01,5767.21 ccw(c5869.76,5771.45) 5865.52,5775.69 5860.73,5770.9 cw(c5856.49,5775.15) 5852.25,5779.39 5857.04,5784.18 ccw(c5852.79,5788.42) 5848.55,5792.66 5843.76,5787.87 cw(c5839.52,5792.12) 5835.28,5796.36 5840.07,5801.15 ccw(c5835.82,5805.39) 5840.07,5809.63 5828.61,5821.09 5737.88,5821.09 v2(5724.17,5807.38)
MIPI_DSI_TX1_D2P: CN3.95 FPC2.10 | length 3420.8
  Top Layer w5: CN3.95@5572.93,5818.07 5597.33,5818.07 5604.1,5824.83 5716.62,5824.83 v2(5723.88,5832.09)
  Bottom Layer w5: FPC2.10@5175.96,4131.49 5124.47,4131.49 5044.47,4051.49 5044.47,3895.96 5118.93,3821.49 5650,3821.49 5968.09,4139.58 5968.09,5697.16 5833.17,5832.09 v2(5723.88,5832.09)
MIPI_DSI_TX1_D3N: CN3.94
MIPI_DSI_TX1_D3P: CN3.96
MIPI_LCD_BL_: R377.1
MIPI_LCD_BL_1: CN4.36
MIPI_LCD_BL_2: CN4.93
MIPI_LCD_EN_1: CN4.18 R73.1 | length 3072.8
  Top Layer w5: R73.1@5014.67,4346.8 4989.47,4372 4989.47,4436.49 5024.47,4471.49 5024.47,4586.49 v2(5064.47,4626.49) ; v2(5399.47,5811.49) 5399.47,5846.49 5759.47,6206.49 5759.47,6256.49 5819.47,6316.49 6119.47,6316.49 6134.69,6301.27 6420.63,6301.27 6455.92,6336.56 CN4.18@6455.92,6359.21
  Bottom Layer w5: v2(5064.47,4626.49) 5084.47,4626.49 5468.47,5010.49 5468.47,5742.49 v2(5399.47,5811.49)
MIPI_LCD_EN_2: CN4.20
MIPI_RESET_1: CN4.83 FPC2.3 | length 3066.4
  Top Layer w5: v2(5888.89,5597.47) 5936.24,5644.82 5936.24,6224.42 5933.46,6227.2 5933.46,6259.3 CN4.83@5933.76,6259.6
  Bottom Layer w5: FPC2.3@5164.47,4019.76 5142.74,4019.76 5134.47,4011.49 5134.47,3936.49 5151.93,3919.03 5607,3919.03 5888.89,4200.91 v2(5888.89,5597.47)
MIPI_RESET_2: CN4.79
MISO: R24.2 U19.40 | length 3332.6
  Top Layer w5: R24.2@5136.51,5271.49 5166.51,5271.49 5189.47,5294.45 5189.47,6291.49 5380.87,6482.89 6330.15,6482.89 6428.42,6581.17 6428.42,6770.44 6539.17,6881.19 6539.17,7011.19 v3(6559.47,7031.49) ; v3(6249.47,7191.49) 6250.99,7193.01 U19.40@6277.97,7193.01
  Bottom Layer w5: v3(6249.47,7191.49) 6304.47,7136.49 6409.47,7136.49 6519.47,7026.49 6554.47,7026.49 v3(6559.47,7031.49)
MOSI: R26.2 U19.39 | length 3175
  Top Layer w5: R26.2@5137.09,5374.48 5159.47,5374.48 5179.47,5394.48 5179.47,6296.49 5374.87,6491.89 6323.51,6491.89 6416.54,6584.92 6416.54,6773.56 6525.99,6883.01 6525.99,7038.01 v3(6534.47,7046.49) ; U19.39@6277.97,7177.27 6315.25,7177.27 v3(6344.47,7206.49)
  Bottom Layer w5: v3(6344.47,7206.49) 6409.47,7206.49 6534.47,7081.49 v3(6534.47,7046.49)
MOSI1: R37.2 U19.16 | length 889
  Top Layer w5: U19.16@6057.2,6987.99 6057.2,6958.76 ccw(c6076.98,6956.07) v3(6059.47,6946.49) ; v3(6114.47,7701.49) 6114.47,7724.82 R37.2@6116.1,7726.46
  Bottom Layer w5: v3(6059.47,6946.49) 6069.47,6956.49 6069.47,7139.24 6016.8,7191.9 6016.8,7582.88 6114.47,7680.55 v3(6114.47,7701.49)
MU-SCL: R370.1 U19.51 U72.8 | length 682.9
  Top Layer w5: U19.51@6120.2,7256.3 6120.2,7271.56 6138.05,7289.41 v3@6138.05,7303.33 ; R370.1@6636.82,7269.75 6668.56,7301.49 6669.47,7301.49 6669.47,7338.35 U72.8@6671.05,7339.93
  Bottom Layer w5: v3(6138.65,7305.08) ccw(c6172.23,7305.08) 6172.23,7271.49 6639.47,7271.49 ccw(c6639.47,7286.49) v3(6654.47,7286.49)
MU-SDA: R371.1 U19.52 U72.9 | length 729.3
  Top Layer w5: U19.52@6104.45,7256.3 6104.45,7285.09 v3(6113.8,7294.43) ; R371.1@6688.38,7269.75 6696.64,7278.01 U72.9@6696.64,7339.93
  Bottom Layer w5: v3(6113.8,7294.43) ccw(c6146.74,7294.43) 6146.74,7261.49 6669.47,7261.49 ccw(c6669.47,7286.49) v3(6694.47,7286.49)
NPWR_LED: CN2.95
NRPIBOOT: CN2.93
NSS: U10.25 U19.45 | length 3052.3
  Top Layer w5: U10.25@5017.97,5586.84 5069.82,5586.84 5159.47,5676.49 5159.47,6306.49 5366.69,6513.72 6316.69,6513.72 6394.47,6591.49 6394.47,6781.49 6504.47,6891.49 6504.47,6991.49 v3(6489.47,7006.49) ; 6214.68,7231.7 U19.45@6214.68,7256.3
  Bottom Layer w5: v3(6214.47,7221.49) 6214.47,7171.49 6279.47,7106.49 6399.47,7106.49 6489.47,7016.49 v3(6489.47,7006.49)
NX1: U19.12
OFF: C98.2 R98.1 R100.1 R102.2 U18.3 U18.4 | length 2523.6
  Top Layer w8: v3(5389.75,6912.91) 5523.05,6912.91 5639.47,6796.49 5964.47,6796.49 6029.47,6731.49 6029.47,6656.49 v3(6009.47,6636.49)
  Bottom Layer w5: U18.4@5110.34,6912.91 v3(5389.75,6912.91) U18.3@5468.6,6912.91 ; v3(6009.47,6636.49) 6035.47,6662.49 6613.47,6662.49 6774.47,6501.49 7040.05,6501.49 R100.1@7099.14,6560.59 7099.71,6561.15 R98.1@7254.47,6561.15
PA1: D1.2 R85.1 R386.1 U72.17 | length 5041.9
  Top Layer w5: D1.2@6407.75,7225.73 6491.99,7141.49 6699.9,7141.49 ; v1(6629.47,6591.49) 6744.47,6706.49 6744.47,7096.92 6699.9,7141.49 ; v2(6797.23,4931.55) 7349.71,4931.55 v1(7405.79,4987.63) 7412.12,4993.96 R85.1@7471.5,4993.96 ; v1(6854.47,7141.49) 6699.9,7141.49 ; U72.17@6861.11,7427.63 6898.33,7427.63 v1(6909.47,7416.49)
  Bottom Layer w5: v1(6629.47,6591.49) 6629.47,5100.31 v2@6799.22,4930.55 ; v1(6854.47,7141.49) 6909.47,7196.49 v1(6909.47,7416.49) ; v1(7405.79,4987.63) 7405.79,5312.82 7574.47,5481.49 8128.26,5481.49 R386.1@8159.79,5513.02
PA_ADC: D1.1 U19.42 | length 161.3
  Top Layer w5: U19.42@6277.97,7224.51 6287.49,7224.51 6363.51,7300.53 D1.1@6407.75,7300.53
PCIE20_CLKREQN_M2: CN3.2
PCIE20_REFCLKN: CN3.12
PCIE20_REFCLKP: CN3.10
PCIE20_RXN: CN3.18
PCIE20_RXP: CN3.16
PCIE20_TXN: CN3.24
PCIE20_TXP: CN3.22
PCIE20_WAKEN: CN4.38
PCIE_NRST: CN3.9
PCIN: R5.2 R374.2 U1.5 U1.6 U1.7 U1.8 U8.7 | length 1079.9
  Top Layer w7.87: U8.7@8195.9,4227.29 8264.95,4227.29 R5.2@8309.73,4272.06
  Bottom Layer w7.87: v4(7464.47,4546.49) 7564.47,4546.49 7669.47,4441.49 8105.19,4441.49 v4(8291.35,4255.33)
